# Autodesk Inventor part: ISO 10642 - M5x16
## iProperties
Created: 2007-08
Part Number: ISO 10642 - M5x16
Material: Stahl, weich, unlegiert
Description: Innensechskantschraube mit Senkkopf
Vendor: Autodesk Inc.
Document SubType Name: Modeling
Standard: ISO 10642
Designer: Ulrich
Standards Organization: ISO
Language: de-DE
Size Designation: M5 x  16
Categories: <MemberInstance Version="R10.0.0"><Categories><Category DisplayName="Schrauben" InternalName="e4da775c-781d-43d5-af7c-5136215cf5a6" Mnemonic="FSTN"><Category Di
Author: Ulrich
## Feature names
1. Körper [Revolution]
2. Loch [Extrusion]
3. Fase1 [Chamfer]
